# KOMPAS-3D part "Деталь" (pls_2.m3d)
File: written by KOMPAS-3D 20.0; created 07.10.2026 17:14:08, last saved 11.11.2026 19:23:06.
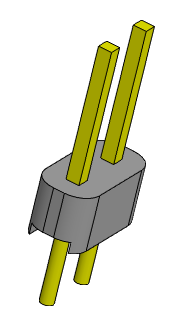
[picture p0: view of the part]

Document properties: Полное имя файла: D:\myProjects\Progect_esp32\box_compas\разъемы\pls_2.m3d

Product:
- Part/product: Деталь
    Масса: 0.000244624

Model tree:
1. Эскиз:1
2. Элемент выдавливания:1
     Расстояние 1 = 2.5
3. Эскиз:2  (with: Элемент выдавливания:1)
4. Элемент выдавливания:2
     Расстояние 1 = 6
5. Массив по сетке:1  (with: Элемент выдавливания:2, Эскиз:2)  (2 pattern instances)
     Шаг 1 = 2.54; Угол раствора = 90
6. Эскиз:3  (with: Элемент выдавливания:1)
7. Элемент выдавливания:3
     Расстояние 1 = 3
8. Массив по сетке:2  (with: Элемент выдавливания:3, Эскиз:3)  (2 pattern instances)
     Шаг 1 = 2.54; Угол раствора = 90; Геометрический массив = 128
9. Эскиз:4  (with: Элемент выдавливания:1)
10. Элемент выдавливания:4
     Расстояние 2 = 5.08
11. Скругление:1  (with: Элемент выдавливания:1)
     Радиус = 1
